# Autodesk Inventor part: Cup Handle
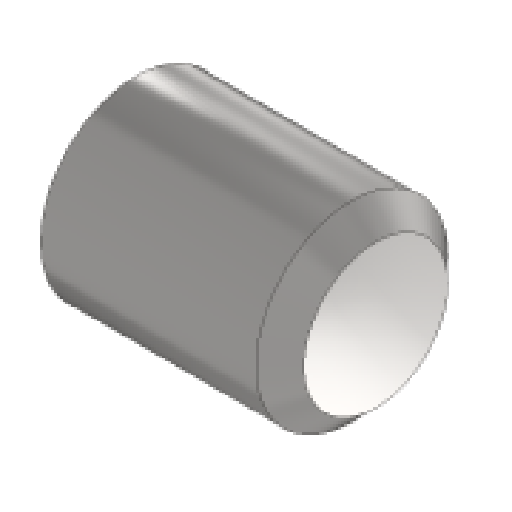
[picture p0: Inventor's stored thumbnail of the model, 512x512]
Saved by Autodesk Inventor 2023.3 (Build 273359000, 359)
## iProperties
Created: 2020-10
Part Number: Cup Handle
Material: Steel, Mild
Document SubType Name: Modeling
Designer: User
Density: 7.85 g/cm^3
Appearance: Semi-Polished
Mass: 2.93061 g
Surface Area: 4.30082 cm^2
Volume: 0.373326 cm^3
Author: User
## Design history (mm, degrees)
sketch "Sketch1"
  geometry: L1 (0, 0)-(10, 0); L2 (10, 0)-(10, 3); L3 (9, 4)-(0, 4); L4 (0, 4)-(0, 0); L5 (10, 3)-(9, 4); L6 (6, 0)-(6, 2.5); L7 (6, 2.5)-(0, 2.5); 1 further point
  constraints: 14 end point, 4 point on line, 3 parallel, 2 perpendicular, 1 horizontal
  dimensions: "d0" = 10 distance of L3.end point (10, 4); "d1" = 4 distance of point (10, 4) L1.end; "d2" = 1 distance of L2.end point (10, 4); "d3" = 1 distance of L3.start point (10, 4) (= d2); "d4" = 2.5 distance of L6.start L6.end; "d5" = 6 distance of L6.end L7.end
revolve "Revolution1" sketch "Sketch1" stored, may be unused: angle "d6" = 90 deg
body "Solid1"
